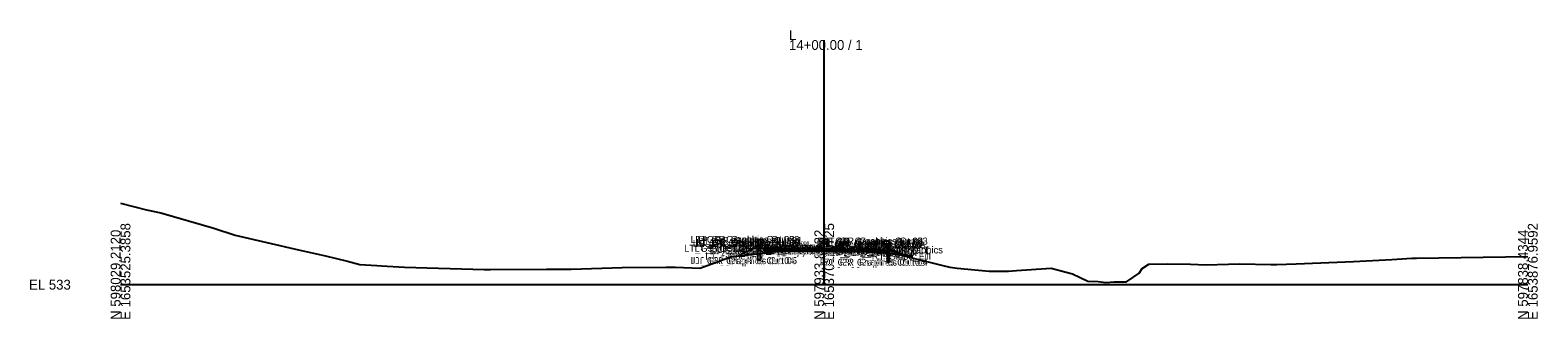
# Model space of a CAD drawing. Extents: x -26 to 403, y -10 to 6021.
# Drawn here: x -25.7 to 402.8, y 2490.3 to 2572.2 of the extents above; entities that cross this region are included whole.
import ezdxf

# ---------------------------------------------------------------- set-up
doc = ezdxf.new("R2010")
doc.units = 0
for name, color, linetype in [('Default', 7, 'Continuous'), ('Exist Cross Section Cell', 7, 'Continuous'), ('Exist XS Ground Line', 7, 'Continuous'), ('Prop CMT Guardrail Graphics', 7, 'Continuous'), ('Prop CMT Pvmt Course 1', 7, 'Continuous'), ('Prop CMT Pvmt Course 2', 7, 'Continuous'), ('Prop CMT Pvmt Course 3', 7, 'Continuous'), ('Prop CMT Pvmt Surface', 7, 'Continuous'), ('Prop CMT Pvmt Surface Shoulder', 7, 'Continuous'), ('Prop CMT Shld Paved Course 1', 7, 'Continuous'), ('Prop CMT Shld Paved Course 2', 7, 'Continuous'), ('Prop CMT Shld Paved Course 3', 7, 'Continuous'), ('Prop CMT Slope Grass', 7, 'Continuous'), ('Prop CMT Subgrade Earthwork', 7, 'Continuous'), ('Prop XS Earthwork Shape', 7, 'Continuous'), ('Prop XS SE Text', 7, 'Continuous'), ('Prop XS Side Slope Text', 7, 'Continuous')]:
    doc.layers.add(name, color=color, linetype=linetype)

msp = doc.modelspace()

# ---------------------------------------------------------------- linework, layer by layer
at = {"layer": 'Exist Cross Section Cell'}
for p, q in [((200, 2500), (200, 2569.44)), ((0, 2500), (200, 2500)), ((200, 2500), (400, 2500))]:
    msp.add_line(p, q, dxfattribs=at)
at = {"layer": 'Exist XS Ground Line'}
msp.add_lwpolyline([(0, 2523.15), (7.39, 2521.23), (11.41, 2520.36), (26.55, 2516.07), (32.62, 2514.03), (50.56, 2509.85), (58.25, 2508.14), (64.53, 2506.66), (68, 2505.76), (72.87, 2505.43), (74.2, 2505.34), (80.69, 2504.93), (103.38, 2504.29), (105.11, 2504.27), (121.11, 2504.39), (128.1, 2504.39), (142.57, 2504.84), (155.03, 2504.92), (157.74, 2504.93), (164.62, 2504.71), (169.08, 2506.31), (173.66, 2508.02), (176.22, 2508.18), (186.21, 2509.38), (188.86, 2509.89), (193.31, 2509.98), (200, 2510.18), (200.65, 2510.2), (208.12, 2510.05), (212.35, 2509.9), (220.03, 2508.62), (221.94, 2508.35), (224.9, 2507.63), (233.7, 2505.44), (235.73, 2504.93), (235.83, 2504.92), (237.81, 2504.71), (246.87, 2503.8), (252.37, 2503.79), (254.68, 2504.05), (264.53, 2504.65), (270.56, 2503.06), (274.96, 2501.03), (277.86, 2500.9), (280.02, 2500.66), (282.44, 2500.79), (285.94, 2500.83), (289.55, 2503.31), (290.38, 2504.55), (292.31, 2505.81), (297.53, 2505.88), (304.12, 2505.78), (308.57, 2505.67), (314.9, 2505.82), (318.18, 2505.9), (326.94, 2505.72), (328.1, 2505.73), (328.64, 2505.73), (334.13, 2505.94), (350.48, 2506.6), (361.37, 2507.19), (367.06, 2507.49), (367.87, 2507.52), (368.31, 2507.52), (400, 2508.04)], dxfattribs=at)
at = {"layer": 'Prop CMT Guardrail Graphics'}
for points in [[(181.13, 2506.83), (181.13, 2512.83)], [(181.13, 2512.83), (182.46, 2512.83), (182.73, 2512.54)], [(182.73, 2511.95), (182.46, 2511.66), (181.8, 2511.66)], [(181.8, 2511.66), (181.8, 2506.83)], [(182.73, 2512.54), (182.46, 2512.24)], [(182.46, 2512.24), (182.73, 2511.95)], [(218.56, 2512.37), (217.23, 2512.37), (216.95, 2512.08)], [(216.95, 2512.08), (217.23, 2511.79)], [(217.23, 2511.79), (216.95, 2511.49)], [(216.95, 2511.49), (217.23, 2511.2), (217.89, 2511.2)], [(217.89, 2511.2), (217.89, 2506.37)], [(218.56, 2506.37), (218.56, 2512.37)], [(181.8, 2506.83), (181.13, 2506.83)], [(217.89, 2506.37), (218.56, 2506.37)]]:
    msp.add_lwpolyline(points, dxfattribs=at)
at = {"layer": 'Prop CMT Pvmt Course 1'}
for points in [[(200, 2510.26), (188, 2510.36)], [(188, 2510.36), (188, 2510.15)], [(188, 2510.15), (200, 2510.06)], [(200, 2510.06), (200, 2510.26)], [(200, 2510.26), (212, 2510.02)], [(200, 2510.06), (200, 2510.26)], [(212, 2509.82), (200, 2510.06)], [(212, 2510.02), (212, 2509.82)]]:
    msp.add_lwpolyline(points, dxfattribs=at)
msp.add_lwpolyline([(200, 2510.06), (200, 2510.06), (200, 2510.06), (200, 2510.06)], close=True, dxfattribs=at)
msp.add_lwpolyline([(200, 2510.06), (200, 2510.06), (200, 2510.06), (200, 2510.06)], close=True, dxfattribs=at)
at = {"layer": 'Prop CMT Pvmt Course 2'}
for points in [[(200, 2510.06), (188, 2510.15)], [(188, 2510.15), (188, 2509.94)], [(188, 2509.94), (200, 2509.85)], [(200, 2509.85), (200, 2510.06)], [(200, 2509.85), (200, 2510.06)], [(200, 2510.06), (212, 2509.82)], [(212, 2509.61), (200, 2509.85)], [(212, 2509.82), (212, 2509.61)]]:
    msp.add_lwpolyline(points, dxfattribs=at)
at = {"layer": 'Prop CMT Pvmt Course 3'}
for points in [[(200, 2509.85), (188, 2509.94)], [(188, 2509.94), (188, 2509.61)], [(188, 2509.61), (200, 2509.52)], [(200, 2509.52), (200, 2509.85)], [(200, 2509.85), (212, 2509.61)], [(200, 2509.52), (200, 2509.85)], [(212, 2509.28), (200, 2509.52)], [(212, 2509.61), (212, 2509.28)]]:
    msp.add_lwpolyline(points, dxfattribs=at)
at = {"layer": 'Prop CMT Pvmt Surface'}
for points in [[(200, 2510.26), (188, 2510.36)], [(200, 2510.26), (212, 2510.02)]]:
    msp.add_lwpolyline(points, dxfattribs=at)
at = {"layer": 'Prop CMT Pvmt Surface Shoulder'}
for points in [[(188, 2510.36), (184, 2510.39)], [(212, 2510.02), (216, 2509.94)]]:
    msp.add_lwpolyline(points, dxfattribs=at)
at = {"layer": 'Prop CMT Shld Paved Course 1'}
for points in [[(188, 2510.36), (184, 2510.39), (183.79, 2510.19)], [(183.79, 2510.19), (188, 2510.15)], [(188, 2510.15), (188, 2510.36)], [(212, 2510.02), (216, 2509.94), (216.21, 2509.73)], [(212, 2509.82), (212, 2510.02)], [(216.21, 2509.73), (212, 2509.82)]]:
    msp.add_lwpolyline(points, dxfattribs=at)
at = {"layer": 'Prop CMT Shld Paved Course 2'}
for points in [[(188, 2510.15), (183.79, 2510.19), (183.59, 2509.98)], [(183.59, 2509.98), (188, 2509.94)], [(188, 2509.94), (188, 2510.15)], [(212, 2509.82), (216.21, 2509.73), (216.43, 2509.52)], [(212, 2509.61), (212, 2509.82)], [(216.43, 2509.52), (212, 2509.61)]]:
    msp.add_lwpolyline(points, dxfattribs=at)
at = {"layer": 'Prop CMT Shld Paved Course 3'}
for points in [[(183.59, 2509.98), (183.26, 2509.65)], [(183.26, 2509.65), (188, 2509.61)], [(188, 2509.94), (183.59, 2509.98)], [(183.59, 2509.98), (183.59, 2509.98)], [(188, 2509.61), (188, 2509.94)], [(212, 2509.61), (216.43, 2509.52)], [(212, 2509.28), (212, 2509.61)], [(216.77, 2509.18), (212, 2509.28)], [(216.43, 2509.52), (216.43, 2509.52)], [(216.43, 2509.52), (216.77, 2509.18)]]:
    msp.add_lwpolyline(points, dxfattribs=at)
at = {"layer": 'Prop CMT Slope Grass'}
for points in [[(184, 2510.39), (179.73, 2510.17), (175.68, 2508.14)], [(179.73, 2510.17), (175.68, 2508.14)], [(182.73, 2510.33), (179.73, 2510.17)], [(184, 2510.39), (182.73, 2510.33)], [(216, 2509.94), (216.95, 2509.87)], [(216.95, 2509.87), (219.95, 2509.63)], [(219.95, 2509.63), (223.03, 2508.09)]]:
    msp.add_lwpolyline(points, dxfattribs=at)
at = {"layer": 'Prop CMT Subgrade Earthwork'}
for points in [[(183.26, 2509.65), (182.59, 2510.32)], [(188, 2509.61), (183.26, 2509.65)], [(200, 2509.52), (188, 2509.61)], [(200, 2509.52), (212, 2509.28)], [(212, 2509.28), (216.77, 2509.18)], [(216.77, 2509.18), (217.42, 2509.83)]]:
    msp.add_lwpolyline(points, dxfattribs=at)
at = {"layer": 'Prop XS Earthwork Shape'}
for points in [[(187.43, 2509.62), (183.26, 2509.65), (182.59, 2510.32), (179.73, 2510.17), (175.68, 2508.14), (176.22, 2508.18), (186.21, 2509.38)], [(187.43, 2509.62), (183.26, 2509.65), (182.59, 2510.32), (179.73, 2510.17), (175.68, 2508.14), (176.22, 2508.18), (186.21, 2509.38)], [(187.43, 2509.62), (183.26, 2509.65), (182.59, 2510.32), (179.73, 2510.17), (175.68, 2508.14), (176.22, 2508.18), (186.21, 2509.38)], [(212, 2509.82), (200, 2510.06), (196.68, 2510.08), (193.31, 2509.98), (188.86, 2509.89), (187.43, 2509.62), (188, 2509.61), (200, 2509.52), (212, 2509.28), (216.67, 2509.18), (212.35, 2509.9), (212, 2509.92)], [(212, 2509.82), (200, 2510.06), (196.68, 2510.08), (193.31, 2509.98), (188.86, 2509.89), (187.43, 2509.62), (188, 2509.61), (200, 2509.52), (212, 2509.28), (216.67, 2509.18), (212.35, 2509.9), (212, 2509.92)], [(212, 2509.82), (200, 2510.06), (196.68, 2510.08), (193.31, 2509.98), (188.86, 2509.89), (187.43, 2509.62), (188, 2509.61), (200, 2509.52), (212, 2509.28), (216.67, 2509.18), (212.35, 2509.9), (212, 2509.92)], [(196.68, 2510.08), (200, 2510.18), (200, 2510.06)], [(196.68, 2510.08), (200, 2510.18), (200, 2510.06)], [(196.68, 2510.08), (200, 2510.18), (200, 2510.06)], [(212, 2509.82), (200, 2510.06), (200, 2510.18), (200.65, 2510.2), (208.12, 2510.05), (212, 2509.92)], [(212, 2509.82), (200, 2510.06), (200, 2510.18), (200.65, 2510.2), (208.12, 2510.05), (212, 2509.92)], [(212, 2509.82), (200, 2510.06), (200, 2510.18), (200.65, 2510.2), (208.12, 2510.05), (212, 2509.92)], [(216.67, 2509.18), (220.03, 2508.62), (221.94, 2508.35), (223.03, 2508.09), (219.95, 2509.63), (217.42, 2509.83), (216.77, 2509.18)], [(216.67, 2509.18), (220.03, 2508.62), (221.94, 2508.35), (223.03, 2508.09), (219.95, 2509.63), (217.42, 2509.83), (216.77, 2509.18)], [(216.67, 2509.18), (220.03, 2508.62), (221.94, 2508.35), (223.03, 2508.09), (219.95, 2509.63), (217.42, 2509.83), (216.77, 2509.18)]]:
    msp.add_lwpolyline(points, close=True, dxfattribs=at)

# ---------------------------------------------------------------- texts
at = {"layer": 'Default'}
for s, height, p in [('LT_GS_OS_GR_Face_Graphics', 2, (160.19, 2509.33)), ('LT_GR_Graphics Out 03', 2, (162.03, 2511.83)), ('LT_GR_Graphics Out 06', 2, (162.65, 2510.66)), ('LT_Sub_Trench_Out_DLT', 2, (163.15, 2509.32)), ('LT_GR_Graphics Out 02', 2, (163.36, 2511.83)), ('LT_GR_Graphics Out 09', 2, (163.36, 2511.24)), ('LT_GR_Graphics Out 07', 2, (163.36, 2510.66)), ('LT_GR_Graphics Out 08', 2, (163.63, 2510.95)), ('LT_GR_Graphics Out 01', 2, (164.2, 2511.54)), ('LT_PS2_OEOP', 2, (174.03, 2509.19)), ('LT_PS1_OEOP', 2, (174.8, 2509.39)), ('LT_PV1_OEOT', 2, (178.74, 2509.36)), ('PV1_PGL', 2, (194.47, 2509.26)), ('RT_GR_Graphics Out 08', 2, (197.8, 2510.49)), ('RT_GR_Graphics Out 02', 2, (198.08, 2511.37)), ('RT_GR_Graphics Out 09', 2, (198.08, 2510.79)), ('RT_GR_Graphics Out 07', 2, (198.08, 2510.2)), ('RT_GR_Graphics Out 01', 2, (198.37, 2511.08)), ('RT_GR_Graphics Out 06', 2, (198.69, 2510.2)), ('RT_GR_Graphics Out 03', 2, (199.41, 2511.37)), ('LT_GR_Graphics Out 04', 2, (162.03, 2505.83)), ('LT_GR_Graphics Out 05', 2, (162.69, 2505.83)), ('LT_Slope_Fill', 2, (166.2, 2507.14)), ('LT_Sub_Trench_Out', 2, (167.46, 2508.65)), ('LT_GS_OS_CTL', 2, (169.1, 2509.17)), ('LT_PS3_Shelf_Out', 2, (169.57, 2508.98)), ('LT_PS3_OEOP', 2, (173.82, 2508.98)), ('LT_Sub_OEOT', 2, (178.08, 2508.61)), ('LT_PV2_OEOT', 2, (178.17, 2509.15)), ('LT_PV3_OEOT', 2, (178.17, 2508.94)), ('RT_Sub_OEEOP', 2, (189.17, 2508.52)), ('LT_Sub_OEEOP', 2, (189.21, 2508.52)), ('RT_PV2_OEEOP', 2, (189.26, 2509.06)), ('RT_PV3_OEEOP', 2, (189.26, 2508.85)), ('LT_PV2_OEEOP', 2, (189.31, 2509.06)), ('LT_PV3_OEEOP', 2, (189.31, 2508.85)), ('RT_PV1_OEEOP', 2, (189.83, 2509.06)), ('LT_PV1_OEEOP', 2, (189.87, 2509.06)), ('RT_PV2_IEEOP', 2, (189.91, 2509.06)), ('LT_PV2_IEEOP', 2, (189.95, 2509.06)), ('RT_PV1_IEEOP', 2, (190.47, 2509.06)), ('LT_PV1_IEEOP', 2, (190.52, 2509.06)), ('PV2_PGL', 2, (193.91, 2509.06)), ('RT_GS_OS_GR_Face_Graphics', 2, (194.36, 2508.87)), ('RT_Sub_Trench_Out_DLT', 2, (197.94, 2508.83)), ('RT_GR_Graphics Out 05', 2, (198.74, 2505.37)), ('RT_GR_Graphics Out 04', 2, (199.41, 2505.37)), ('RT_Sub_Trench_Out', 2, (200.92, 2508.18)), ('RT_Sub_OEOT', 2, (202.03, 2508.28)), ('RT_PV2_OEOT', 2, (202.13, 2508.82)), ('RT_PV3_OEOT', 2, (202.13, 2508.61)), ('RT_PS3_Shelf_Out', 2, (202.36, 2508.52)), ('RT_PV1_OEOT', 2, (202.69, 2509.02)), ('RT_PS2_OEOP', 2, (206.4, 2508.73)), ('RT_PS3_OEOP', 2, (206.61, 2508.52)), ('RT_PS1_OEOP', 2, (206.76, 2508.94)), ('RT_GS_OS_CTL', 2, (209.28, 2508.63)), ('RT_Slope_Fill', 2, (213.51, 2507.09)), ('-', 0.0001, (0, 2500))]:
    msp.add_text(s, height=height, dxfattribs=at).set_placement(p)
at = {"layer": 'Exist Cross Section Cell'}
for s, p in [('L', (190, 2569.44)), ('14+00.00 / 1', (190, 2566.64)), ('EL 533', (-26, 2498.6))]:
    msp.add_text(s, height=2.8, dxfattribs=at).set_placement(p)
for s, p in [('E 1653525.3858', (2.8, 2490)), ('E 1653701.1725', (202.8, 2490)), ('N 597838.4344', (400, 2490)), ('E 1653876.9592', (402.8, 2490)), ('N 598029.2120', (0, 2490)), ('N 597933.8232', (200, 2490))]:
    msp.add_text(s, height=2.8, rotation=90, dxfattribs=at).set_placement(p)
at = {"layer": 'Prop XS SE Text'}
for s, rotation, p in [('0.008', 359.5416, (192.27, 2511.33)), ('0.020', 358.8542, (204.27, 2511.18))]:
    msp.add_text(s, height=1, rotation=rotation, dxfattribs=at).set_placement(p)
at = {"layer": 'Prop XS Side Slope Text'}
for rotation, p in [(26.5651, (176.66, 2509.47)), (333.4349, (221.12, 2509.88))]:
    msp.add_text('2:1', height=1, rotation=rotation, dxfattribs=at).set_placement(p)

doc.saveas('drawing.dxf')
